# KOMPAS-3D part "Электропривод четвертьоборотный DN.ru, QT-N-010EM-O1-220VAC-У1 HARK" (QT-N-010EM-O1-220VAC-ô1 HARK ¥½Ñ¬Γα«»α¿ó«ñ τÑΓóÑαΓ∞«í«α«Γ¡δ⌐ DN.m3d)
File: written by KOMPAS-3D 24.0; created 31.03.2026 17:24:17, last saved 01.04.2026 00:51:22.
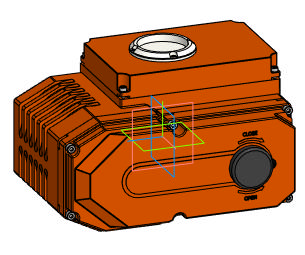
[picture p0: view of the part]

Document properties: Автор: DN.RU; Полное имя файла: D:\PROJECT CAD\DN.RU\...195\Исходники\220В\QT-N-010EM-O1-220VAC-У1 HARK Электропривод четвертьоборотный DN.ru\QT-N-010EM-O1-220VAC-У1 HARK Электропривод четвертьоборотный DN.m3d

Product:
- Body: Твердое тело1  | qty 1
    Масса: 18.642153
- Part/product: Электропривод четвертьоборотный DN.ru  | designation QT-N-010EM-O1-220VAC-У1 HARK
    Масса: 4.6
    Раздел спецификации: Прочие изделия
    Комментарий: D300-14484
    Примечание: D300-14483
    additional columns: Сталь

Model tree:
1. Твердое тело1  (labels: Твердое тело1)

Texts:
  QT-N-010EM-O1-220VAC-У1 HARK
